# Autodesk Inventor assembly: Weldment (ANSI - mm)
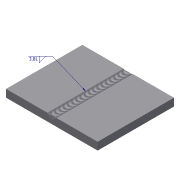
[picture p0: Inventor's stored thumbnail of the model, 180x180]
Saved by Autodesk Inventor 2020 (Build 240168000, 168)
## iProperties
Length Units: 11269
Angle Units: 11283
Time Units: 11279
Mass Units: 11290
Length Display Precision: 3
Angle Display Precision: 2
Part Number: Weldment (ANSI - mm)
Document SubType Name: Weldment
Created: 2002-06
Designer: smithga
Shininess: 64.0
Angle Units: 11279
Time Units: 11290
Mass Units: 11283
Compacted: True
Part Number: fig 16-6
Created: 2003-01
Designer: Owner
Density: 0.0
Volumn: 0.0
Area: 0.0
PropertySet Name: Model Information
Control State: 0
Master: False
Author: Owner
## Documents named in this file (2)
- D:\Autodesk Inventor_2020\Resources\Resources\Inventor_2020_Part\Inventor_2020_Part\c16_Inv_2020_prt\fig 16-6\fig 16-6.iam
- D:\Autodesk Inventor_2020\Resources\Resources\Inventor_2020_Part\Inventor_2020_Part\c16_Inv_2020_prt\fig 16-6\Part1.ipt
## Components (2 placed, 1 different names)
1. Part1:1 — Mate:1, Flush:1, Flush:2
2. Part1:2 — Mate:1, Flush:1, Flush:2
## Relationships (3: Flush 2, Mate 1)
- Mate:1: Part1:1 ↔ Part1:2
- Flush:1: Part1:1 ↔ Part1:2
- Flush:2: Part1:1 ↔ Part1:2
